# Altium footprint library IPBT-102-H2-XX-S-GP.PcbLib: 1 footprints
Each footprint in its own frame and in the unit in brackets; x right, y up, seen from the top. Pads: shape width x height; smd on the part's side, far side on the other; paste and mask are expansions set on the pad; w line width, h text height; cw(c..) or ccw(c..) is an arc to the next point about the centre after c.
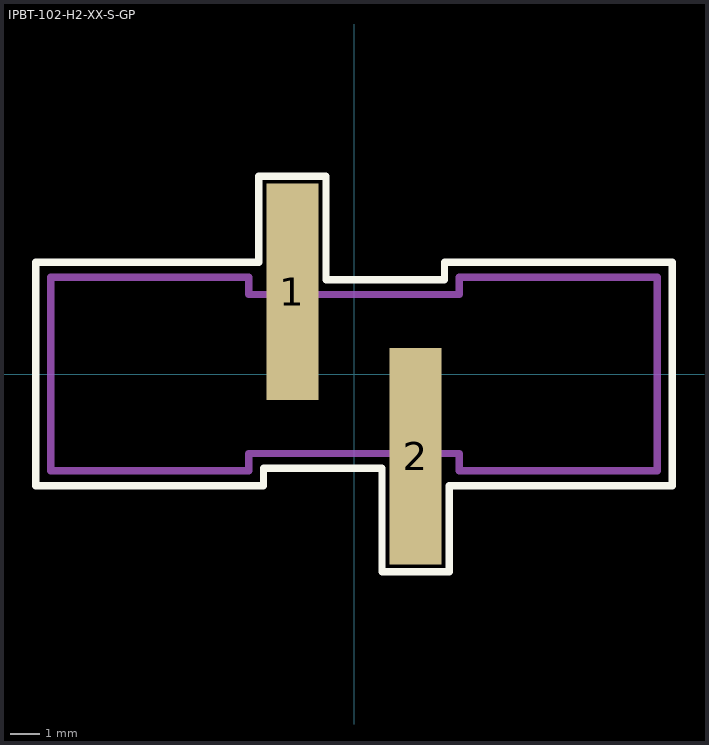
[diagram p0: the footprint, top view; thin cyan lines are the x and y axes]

## IPBT-102-H2-XX-S-GP [mil]
pads (2):
  rect 70x290 smd mask+2: 1(-82.5,110) 2(82.5,-110)
Top Overlay:
  lines w10: -426.25,-149.5 -426.25,149.5 -127.5,149.5 -127.5,265 -37.5,265 -37.5,126.5 121.25,126.5 121.25,149.5 426.25,149.5 426.25,-149.5 127.5,-149.5 127.5,-265 37.5,-265 37.5,-126.5 -121.25,-126.5 -121.25,-149.5 -426.25,-149.5
Mechanical 1:
  lines w10: -406.25,-129.5 -406.25,129.5 -141.25,129.5 -141.25,106.5 141.25,106.5 141.25,129.5 406.25,129.5 406.25,-129.5 141.25,-129.5 141.25,-106.5 -141.25,-106.5 -141.25,-129.5 -406.25,-129.5
  text "J1" at -17.57,-18 h30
